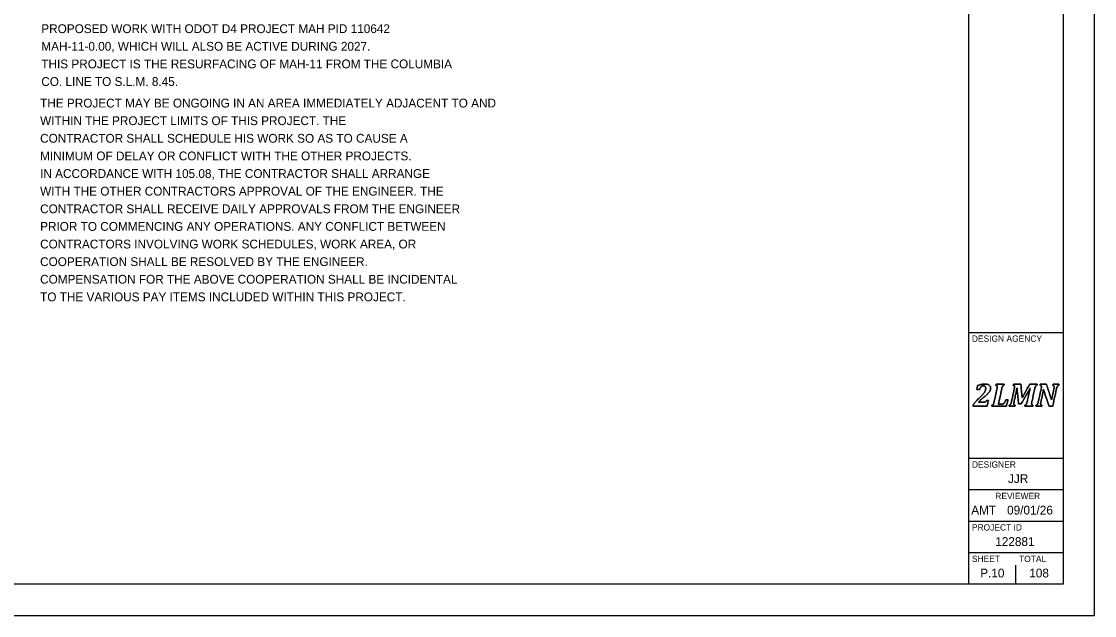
# Model space of a CAD drawing. Extents: x 0 to 34, y 0 to 22.
# Drawn here: x 16.93 to 34, y 0 to 9.44 of the extents above; entities that cross this region are included whole.
import ezdxf

# ---------------------------------------------------------------- set-up
doc = ezdxf.new("R2010")
doc.units = 0
for name, color, linetype in [('SH_Border', 7, 'Continuous'), ('SH_Cut_Line', 7, 'Continuous'), ('SH_Data', 7, 'Continuous'), ('SH_Text', 7, 'Continuous')]:
    doc.layers.add(name, color=color, linetype=linetype)

msp = doc.modelspace()

# ---------------------------------------------------------------- linework, layer by layer
at = {"layer": 'SH_Border'}
for p, q in [((32, 0.5), (32, 21.5)), ((32, 4.5), (33.5, 4.5)), ((32, 2.5), (33.5, 2.5)), ((32, 2), (33.5, 2)), ((32, 1.5), (33.5, 1.5)), ((32, 1), (33.5, 1))]:
    msp.add_line(p, q, dxfattribs=at)
msp.add_lwpolyline([(1.5, 21.5), (33.5, 21.5), (33.5, 0.5), (1.5, 0.5)], close=True, dxfattribs=at)
at = {"layer": 'SH_Cut_Line'}
msp.add_lwpolyline([(0, 0), (34, 0), (34, 22), (0, 22)], close=True, dxfattribs=at)
at = {"layer": 'SH_Data'}
for p, q in [((32.75, 3.5), (32.75, 3.5)), ((32.75, 0.5), (32.75, 0.8)), ((32.375, 0.675), (32.375, 0.675))]:
    msp.add_line(p, q, dxfattribs=at)
for points in [[(32.237, 3.388), (32.246, 3.388), (32.253, 3.389), (32.258, 3.39), (32.263, 3.392), (32.267, 3.394), (32.27, 3.397), (32.273, 3.401), (32.277, 3.408), (32.281, 3.417), (32.281, 3.417), (32.312, 3.417), (32.312, 3.417), (32.312, 3.417), (32.29, 3.326), (32.29, 3.326), (32.29, 3.326), (32.066, 3.326), (32.066, 3.326), (32.066, 3.326), (32.069, 3.343), (32.069, 3.343), (32.078, 3.358), (32.091, 3.375), (32.106, 3.394), (32.122, 3.412), (32.144, 3.435), (32.172, 3.462), (32.197, 3.486), (32.217, 3.506), (32.23, 3.521), (32.243, 3.537), (32.253, 3.551), (32.259, 3.566), (32.266, 3.58), (32.269, 3.595), (32.269, 3.61), (32.269, 3.622), (32.266, 3.632), (32.26, 3.64), (32.253, 3.647), (32.245, 3.65), (32.234, 3.65), (32.22, 3.65), (32.208, 3.646), (32.198, 3.636), (32.188, 3.627), (32.18, 3.613), (32.172, 3.593), (32.172, 3.593), (32.126, 3.593), (32.126, 3.593), (32.126, 3.593), (32.14, 3.654), (32.14, 3.654), (32.166, 3.663), (32.188, 3.669), (32.205, 3.673), (32.223, 3.676), (32.24, 3.678), (32.258, 3.678), (32.278, 3.678), (32.295, 3.675), (32.309, 3.669), (32.322, 3.664), (32.332, 3.656), (32.339, 3.646), (32.345, 3.637), (32.348, 3.626), (32.348, 3.613), (32.348, 3.602), (32.346, 3.591), (32.342, 3.581), (32.339, 3.571), (32.333, 3.56), (32.324, 3.549), (32.315, 3.539), (32.304, 3.526), (32.289, 3.513), (32.275, 3.499), (32.254, 3.482), (32.228, 3.46), (32.216, 3.45), (32.202, 3.438), (32.188, 3.425), (32.174, 3.412), (32.162, 3.4), (32.154, 3.391), (32.154, 3.391), (32.153, 3.388), (32.153, 3.388), (32.153, 3.388), (32.237, 3.388), (32.237, 3.388)], [(32.237, 3.388), (32.237, 3.388), (32.153, 3.388), (32.153, 3.388), (32.153, 3.388), (32.154, 3.391), (32.154, 3.391), (32.162, 3.4), (32.174, 3.412), (32.188, 3.425), (32.202, 3.438), (32.216, 3.45), (32.228, 3.46), (32.254, 3.482), (32.275, 3.499), (32.289, 3.513), (32.304, 3.526), (32.315, 3.539), (32.324, 3.549), (32.333, 3.56), (32.339, 3.571), (32.342, 3.581), (32.346, 3.591), (32.348, 3.602), (32.348, 3.613), (32.348, 3.626), (32.345, 3.637), (32.339, 3.646), (32.332, 3.656), (32.322, 3.664), (32.309, 3.669), (32.295, 3.675), (32.278, 3.678), (32.258, 3.678), (32.24, 3.678), (32.223, 3.676), (32.205, 3.673), (32.188, 3.669), (32.166, 3.663), (32.14, 3.654), (32.14, 3.654), (32.126, 3.593), (32.126, 3.593), (32.126, 3.593), (32.172, 3.593), (32.172, 3.593), (32.18, 3.613), (32.188, 3.627), (32.198, 3.636), (32.208, 3.646), (32.22, 3.65), (32.234, 3.65), (32.245, 3.65), (32.253, 3.647), (32.26, 3.64), (32.266, 3.632), (32.269, 3.622), (32.269, 3.61), (32.269, 3.595), (32.266, 3.58), (32.259, 3.566), (32.253, 3.551), (32.243, 3.537), (32.23, 3.521), (32.217, 3.506), (32.197, 3.486), (32.172, 3.462), (32.144, 3.435), (32.122, 3.412), (32.106, 3.394), (32.091, 3.375), (32.078, 3.358), (32.069, 3.343), (32.069, 3.343), (32.066, 3.326), (32.066, 3.326), (32.066, 3.326), (32.29, 3.326), (32.29, 3.326), (32.29, 3.326), (32.312, 3.417), (32.312, 3.417), (32.312, 3.417), (32.281, 3.417), (32.281, 3.417), (32.277, 3.408), (32.273, 3.401), (32.27, 3.397), (32.267, 3.394), (32.263, 3.392), (32.258, 3.39), (32.253, 3.389), (32.246, 3.388), (32.237, 3.388)], [(32.518, 3.356), (32.527, 3.356), (32.533, 3.357), (32.538, 3.358), (32.542, 3.36), (32.546, 3.362), (32.55, 3.365), (32.554, 3.368), (32.558, 3.372), (32.562, 3.377), (32.567, 3.382), (32.571, 3.388), (32.576, 3.397), (32.58, 3.405), (32.585, 3.415), (32.589, 3.427), (32.589, 3.427), (32.624, 3.427), (32.624, 3.427), (32.624, 3.427), (32.598, 3.326), (32.598, 3.326), (32.598, 3.326), (32.365, 3.326), (32.365, 3.326), (32.365, 3.326), (32.369, 3.343), (32.369, 3.343), (32.376, 3.345), (32.381, 3.348), (32.385, 3.351), (32.389, 3.355), (32.392, 3.36), (32.395, 3.366), (32.398, 3.373), (32.4, 3.382), (32.403, 3.395), (32.403, 3.395), (32.449, 3.605), (32.449, 3.605), (32.452, 3.615), (32.453, 3.625), (32.453, 3.635), (32.453, 3.642), (32.451, 3.647), (32.448, 3.651), (32.444, 3.654), (32.439, 3.656), (32.432, 3.657), (32.432, 3.657), (32.435, 3.674), (32.435, 3.674), (32.435, 3.674), (32.563, 3.674), (32.563, 3.674), (32.563, 3.674), (32.559, 3.657), (32.559, 3.657), (32.552, 3.655), (32.547, 3.652), (32.543, 3.649), (32.539, 3.645), (32.536, 3.64), (32.533, 3.634), (32.531, 3.627), (32.528, 3.618), (32.525, 3.605), (32.525, 3.605), (32.47, 3.356), (32.47, 3.356), (32.47, 3.356), (32.518, 3.356), (32.518, 3.356)], [(32.518, 3.356), (32.518, 3.356), (32.47, 3.356), (32.47, 3.356), (32.47, 3.356), (32.525, 3.605), (32.525, 3.605), (32.528, 3.618), (32.531, 3.627), (32.533, 3.634), (32.536, 3.64), (32.539, 3.645), (32.543, 3.649), (32.547, 3.652), (32.552, 3.655), (32.559, 3.657), (32.559, 3.657), (32.563, 3.674), (32.563, 3.674), (32.563, 3.674), (32.435, 3.674), (32.435, 3.674), (32.435, 3.674), (32.432, 3.657), (32.432, 3.657), (32.439, 3.656), (32.444, 3.654), (32.448, 3.651), (32.451, 3.647), (32.453, 3.642), (32.453, 3.635), (32.453, 3.625), (32.452, 3.615), (32.449, 3.605), (32.449, 3.605), (32.403, 3.395), (32.403, 3.395), (32.4, 3.382), (32.398, 3.373), (32.395, 3.366), (32.392, 3.36), (32.389, 3.355), (32.385, 3.351), (32.381, 3.348), (32.376, 3.345), (32.369, 3.343), (32.369, 3.343), (32.365, 3.326), (32.365, 3.326), (32.365, 3.326), (32.598, 3.326), (32.598, 3.326), (32.598, 3.326), (32.624, 3.427), (32.624, 3.427), (32.624, 3.427), (32.589, 3.427), (32.589, 3.427), (32.585, 3.415), (32.58, 3.405), (32.576, 3.397), (32.571, 3.388), (32.567, 3.382), (32.562, 3.377), (32.558, 3.372), (32.554, 3.368), (32.55, 3.365), (32.546, 3.362), (32.542, 3.36), (32.538, 3.358), (32.533, 3.357), (32.527, 3.356), (32.518, 3.356)], [(32.829, 3.674), (32.829, 3.674), (32.849, 3.461), (32.849, 3.461), (32.849, 3.461), (32.969, 3.674), (32.969, 3.674), (32.969, 3.674), (33.087, 3.674), (33.087, 3.674), (33.087, 3.674), (33.084, 3.657), (33.084, 3.657), (33.077, 3.655), (33.071, 3.652), (33.067, 3.649), (33.064, 3.645), (33.06, 3.64), (33.058, 3.634), (33.055, 3.627), (33.052, 3.618), (33.05, 3.605), (33.05, 3.605), (33.003, 3.395), (33.003, 3.395), (33.002, 3.39), (33.002, 3.387), (33.001, 3.384), (33.001, 3.382), (33.001, 3.379), (33, 3.376), (33, 3.373), (33, 3.369), (33, 3.365), (33, 3.358), (33.002, 3.353), (33.005, 3.349), (33.008, 3.346), (33.014, 3.344), (33.021, 3.343), (33.021, 3.343), (33.018, 3.326), (33.018, 3.326), (33.018, 3.326), (32.89, 3.326), (32.89, 3.326), (32.89, 3.326), (32.893, 3.343), (32.893, 3.343), (32.9, 3.345), (32.906, 3.348), (32.91, 3.351), (32.914, 3.355), (32.917, 3.36), (32.919, 3.366), (32.922, 3.373), (32.925, 3.382), (32.928, 3.395), (32.928, 3.395), (32.951, 3.502), (32.951, 3.502), (32.954, 3.513), (32.957, 3.529), (32.962, 3.548), (32.967, 3.568), (32.972, 3.588), (32.978, 3.609), (32.978, 3.609), (32.973, 3.609), (32.973, 3.609), (32.965, 3.594), (32.957, 3.579), (32.948, 3.563), (32.948, 3.563), (32.833, 3.364), (32.833, 3.364), (32.833, 3.364), (32.792, 3.364), (32.792, 3.364), (32.792, 3.364), (32.775, 3.518), (32.775, 3.518), (32.773, 3.537), (32.772, 3.554), (32.77, 3.569), (32.769, 3.583), (32.768, 3.597), (32.768, 3.611), (32.768, 3.611), (32.764, 3.611), (32.764, 3.611), (32.761, 3.596), (32.758, 3.578), (32.755, 3.558), (32.751, 3.538), (32.747, 3.521), (32.744, 3.507), (32.744, 3.507), (32.72, 3.395), (32.72, 3.395), (32.719, 3.39), (32.718, 3.387), (32.718, 3.384), (32.717, 3.382), (32.717, 3.379), (32.717, 3.376), (32.717, 3.373), (32.716, 3.369), (32.716, 3.365), (32.716, 3.358), (32.718, 3.353), (32.721, 3.349), (32.725, 3.346), (32.73, 3.344), (32.738, 3.343), (32.738, 3.343), (32.734, 3.326), (32.734, 3.326), (32.734, 3.326), (32.641, 3.326), (32.641, 3.326), (32.641, 3.326), (32.644, 3.343), (32.644, 3.343), (32.651, 3.345), (32.657, 3.348), (32.661, 3.351), (32.665, 3.355), (32.668, 3.36), (32.67, 3.366), (32.673, 3.373), (32.676, 3.382), (32.679, 3.395), (32.679, 3.395), (32.725, 3.605), (32.725, 3.605), (32.727, 3.615), (32.728, 3.625), (32.728, 3.635), (32.728, 3.642), (32.727, 3.647), (32.723, 3.651), (32.72, 3.654), (32.715, 3.656), (32.707, 3.657), (32.707, 3.657), (32.711, 3.674), (32.711, 3.674), (32.711, 3.674), (32.829, 3.674), (32.829, 3.674)], [(32.829, 3.674), (32.829, 3.674), (32.711, 3.674), (32.711, 3.674), (32.711, 3.674), (32.707, 3.657), (32.707, 3.657), (32.715, 3.656), (32.72, 3.654), (32.723, 3.651), (32.727, 3.647), (32.728, 3.642), (32.728, 3.635), (32.728, 3.625), (32.727, 3.615), (32.725, 3.605), (32.725, 3.605), (32.679, 3.395), (32.679, 3.395), (32.676, 3.382), (32.673, 3.373), (32.67, 3.366), (32.668, 3.36), (32.665, 3.355), (32.661, 3.351), (32.657, 3.348), (32.651, 3.345), (32.644, 3.343), (32.644, 3.343), (32.641, 3.326), (32.641, 3.326), (32.641, 3.326), (32.734, 3.326), (32.734, 3.326), (32.734, 3.326), (32.738, 3.343), (32.738, 3.343), (32.73, 3.344), (32.725, 3.346), (32.721, 3.349), (32.718, 3.353), (32.716, 3.358), (32.716, 3.365), (32.716, 3.369), (32.717, 3.373), (32.717, 3.376), (32.717, 3.379), (32.717, 3.382), (32.718, 3.384), (32.718, 3.387), (32.719, 3.39), (32.72, 3.395), (32.72, 3.395), (32.744, 3.507), (32.744, 3.507), (32.747, 3.521), (32.751, 3.538), (32.755, 3.558), (32.758, 3.578), (32.761, 3.596), (32.764, 3.611), (32.764, 3.611), (32.768, 3.611), (32.768, 3.611), (32.768, 3.597), (32.769, 3.583), (32.77, 3.569), (32.772, 3.554), (32.773, 3.537), (32.775, 3.518), (32.775, 3.518), (32.792, 3.364), (32.792, 3.364), (32.792, 3.364), (32.833, 3.364), (32.833, 3.364), (32.833, 3.364), (32.948, 3.563), (32.948, 3.563), (32.957, 3.579), (32.965, 3.594), (32.973, 3.609), (32.973, 3.609), (32.978, 3.609), (32.978, 3.609), (32.972, 3.588), (32.967, 3.568), (32.962, 3.548), (32.957, 3.529), (32.954, 3.513), (32.951, 3.502), (32.951, 3.502), (32.928, 3.395), (32.928, 3.395), (32.925, 3.382), (32.922, 3.373), (32.919, 3.366), (32.917, 3.36), (32.914, 3.355), (32.91, 3.351), (32.906, 3.348), (32.9, 3.345), (32.893, 3.343), (32.893, 3.343), (32.89, 3.326), (32.89, 3.326), (32.89, 3.326), (33.018, 3.326), (33.018, 3.326), (33.018, 3.326), (33.021, 3.343), (33.021, 3.343), (33.014, 3.344), (33.008, 3.346), (33.005, 3.349), (33.002, 3.353), (33, 3.358), (33, 3.365), (33, 3.369), (33, 3.373), (33, 3.376), (33.001, 3.379), (33.001, 3.382), (33.001, 3.384), (33.002, 3.387), (33.002, 3.39), (33.003, 3.395), (33.003, 3.395), (33.05, 3.605), (33.05, 3.605), (33.052, 3.618), (33.055, 3.627), (33.058, 3.634), (33.06, 3.64), (33.064, 3.645), (33.067, 3.649), (33.071, 3.652), (33.077, 3.655), (33.084, 3.657), (33.084, 3.657), (33.087, 3.674), (33.087, 3.674), (33.087, 3.674), (32.969, 3.674), (32.969, 3.674), (32.969, 3.674), (32.849, 3.461), (32.849, 3.461), (32.849, 3.461), (32.829, 3.674), (32.829, 3.674)], [(33.137, 3.674), (33.137, 3.674), (33.234, 3.674), (33.234, 3.674), (33.234, 3.674), (33.283, 3.53), (33.283, 3.53), (33.296, 3.49), (33.307, 3.456), (33.315, 3.426), (33.315, 3.426), (33.318, 3.426), (33.318, 3.426), (33.323, 3.455), (33.329, 3.488), (33.337, 3.523), (33.337, 3.523), (33.355, 3.605), (33.355, 3.605), (33.357, 3.615), (33.358, 3.625), (33.358, 3.635), (33.358, 3.642), (33.357, 3.647), (33.353, 3.651), (33.35, 3.654), (33.345, 3.656), (33.337, 3.657), (33.337, 3.657), (33.341, 3.674), (33.341, 3.674), (33.341, 3.674), (33.434, 3.674), (33.434, 3.674), (33.434, 3.674), (33.431, 3.657), (33.431, 3.657), (33.424, 3.655), (33.418, 3.652), (33.414, 3.649), (33.41, 3.645), (33.407, 3.64), (33.405, 3.634), (33.402, 3.627), (33.399, 3.618), (33.396, 3.605), (33.396, 3.605), (33.335, 3.326), (33.335, 3.326), (33.335, 3.326), (33.277, 3.326), (33.277, 3.326), (33.277, 3.326), (33.216, 3.504), (33.216, 3.504), (33.211, 3.518), (33.207, 3.531), (33.204, 3.543), (33.2, 3.556), (33.195, 3.571), (33.19, 3.59), (33.19, 3.59), (33.186, 3.59), (33.186, 3.59), (33.185, 3.579), (33.182, 3.563), (33.179, 3.543), (33.175, 3.523), (33.17, 3.501), (33.165, 3.478), (33.165, 3.478), (33.147, 3.395), (33.147, 3.395), (33.146, 3.39), (33.145, 3.387), (33.145, 3.384), (33.144, 3.382), (33.144, 3.379), (33.144, 3.376), (33.143, 3.373), (33.143, 3.369), (33.143, 3.365), (33.143, 3.358), (33.145, 3.353), (33.148, 3.349), (33.152, 3.346), (33.157, 3.344), (33.164, 3.343), (33.164, 3.343), (33.161, 3.326), (33.161, 3.326), (33.161, 3.326), (33.067, 3.326), (33.067, 3.326), (33.067, 3.326), (33.071, 3.343), (33.071, 3.343), (33.078, 3.345), (33.083, 3.348), (33.087, 3.351), (33.091, 3.355), (33.094, 3.36), (33.097, 3.366), (33.1, 3.373), (33.102, 3.382), (33.105, 3.395), (33.105, 3.395), (33.151, 3.605), (33.151, 3.605), (33.154, 3.615), (33.155, 3.625), (33.155, 3.635), (33.155, 3.642), (33.153, 3.647), (33.15, 3.651), (33.146, 3.654), (33.141, 3.656), (33.134, 3.657), (33.134, 3.657), (33.137, 3.674), (33.137, 3.674)], [(33.137, 3.674), (33.137, 3.674), (33.134, 3.657), (33.134, 3.657), (33.141, 3.656), (33.146, 3.654), (33.15, 3.651), (33.153, 3.647), (33.155, 3.642), (33.155, 3.635), (33.155, 3.625), (33.154, 3.615), (33.151, 3.605), (33.151, 3.605), (33.105, 3.395), (33.105, 3.395), (33.102, 3.382), (33.1, 3.373), (33.097, 3.366), (33.094, 3.36), (33.091, 3.355), (33.087, 3.351), (33.083, 3.348), (33.078, 3.345), (33.071, 3.343), (33.071, 3.343), (33.067, 3.326), (33.067, 3.326), (33.067, 3.326), (33.161, 3.326), (33.161, 3.326), (33.161, 3.326), (33.164, 3.343), (33.164, 3.343), (33.157, 3.344), (33.152, 3.346), (33.148, 3.349), (33.145, 3.353), (33.143, 3.358), (33.143, 3.365), (33.143, 3.369), (33.143, 3.373), (33.144, 3.376), (33.144, 3.379), (33.144, 3.382), (33.145, 3.384), (33.145, 3.387), (33.146, 3.39), (33.147, 3.395), (33.147, 3.395), (33.165, 3.478), (33.165, 3.478), (33.17, 3.501), (33.175, 3.523), (33.179, 3.543), (33.182, 3.563), (33.185, 3.579), (33.186, 3.59), (33.186, 3.59), (33.19, 3.59), (33.19, 3.59), (33.195, 3.571), (33.2, 3.556), (33.204, 3.543), (33.207, 3.531), (33.211, 3.518), (33.216, 3.504), (33.216, 3.504), (33.277, 3.326), (33.277, 3.326), (33.277, 3.326), (33.335, 3.326), (33.335, 3.326), (33.335, 3.326), (33.396, 3.605), (33.396, 3.605), (33.399, 3.618), (33.402, 3.627), (33.405, 3.634), (33.407, 3.64), (33.41, 3.645), (33.414, 3.649), (33.418, 3.652), (33.424, 3.655), (33.431, 3.657), (33.431, 3.657), (33.434, 3.674), (33.434, 3.674), (33.434, 3.674), (33.341, 3.674), (33.341, 3.674), (33.341, 3.674), (33.337, 3.657), (33.337, 3.657), (33.345, 3.656), (33.35, 3.654), (33.353, 3.651), (33.357, 3.647), (33.358, 3.642), (33.358, 3.635), (33.358, 3.625), (33.357, 3.615), (33.355, 3.605), (33.355, 3.605), (33.337, 3.523), (33.337, 3.523), (33.329, 3.488), (33.323, 3.455), (33.318, 3.426), (33.318, 3.426), (33.315, 3.426), (33.315, 3.426), (33.307, 3.456), (33.296, 3.49), (33.283, 3.53), (33.283, 3.53), (33.234, 3.674), (33.234, 3.674), (33.234, 3.674), (33.137, 3.674), (33.137, 3.674)]]:
    msp.add_open_spline(points, degree=3, dxfattribs=at)

# ---------------------------------------------------------------- texts
for s, height, p in [('DESIGN AGENCY', 0.1, (32.05, 4.35)), ('DESIGNER', 0.1, (32.05, 2.35)), ('JJR', 0.14, (32.624, 2.105)), ('REVIEWER', 0.1, (32.422, 1.85)), ('AMT', 0.14, (32.039, 1.605)), ('09/01/26', 0.14, (32.609, 1.605)), ('PROJECT ID', 0.1, (32.05, 1.35)), ('122881', 0.14, (32.421, 1.105)), ('SHEET', 0.1, (32.05, 0.85)), ('TOTAL', 0.1, (32.8, 0.85)), ('P.10', 0.14, (32.182, 0.605)), ('108', 0.14, (32.962, 0.605))]:
    msp.add_text(s, height=height, dxfattribs=at).set_placement(p)
at = {"layer": 'SH_Text'}
for s, p in [('PROPOSED WORK WITH ODOT D4 PROJECT MAH PID 110642', (17.25, 9.255)), ('MAH-11-0.00, WHICH WILL ALSO BE ACTIVE DURING 2027.', (17.25, 8.975)), ('THIS PROJECT IS THE RESURFACING OF MAH-11 FROM THE COLUMBIA', (17.25, 8.695)), ('CO. LINE TO S.L.M. 8.45.', (17.25, 8.415)), ('THE PROJECT MAY BE ONGOING IN AN AREA IMMEDIATELY ADJACENT TO AND', (17.231, 8.073)), ('WITHIN THE PROJECT LIMITS OF THIS PROJECT. THE', (17.231, 7.793)), ('CONTRACTOR SHALL SCHEDULE HIS WORK SO AS TO CAUSE A', (17.231, 7.513)), ('MINIMUM OF DELAY OR CONFLICT WITH THE OTHER PROJECTS.', (17.231, 7.233)), ('IN ACCORDANCE WITH 105.08, THE CONTRACTOR SHALL ARRANGE', (17.231, 6.953)), ('WITH THE OTHER CONTRACTORS APPROVAL OF THE ENGINEER. THE', (17.231, 6.673)), ('CONTRACTOR SHALL RECEIVE DAILY APPROVALS FROM THE ENGINEER', (17.231, 6.393)), ('PRIOR TO COMMENCING ANY OPERATIONS. ANY CONFLICT BETWEEN', (17.231, 6.113)), ('CONTRACTORS INVOLVING WORK SCHEDULES, WORK AREA, OR', (17.231, 5.833)), ('COOPERATION SHALL BE RESOLVED BY THE ENGINEER.', (17.231, 5.553)), ('COMPENSATION FOR THE ABOVE COOPERATION SHALL BE INCIDENTAL', (17.231, 5.273)), ('TO THE VARIOUS PAY ITEMS INCLUDED WITHIN THIS PROJECT.', (17.231, 4.993))]:
    msp.add_text(s, height=0.14, dxfattribs=at).set_placement(p)

doc.saveas('drawing.dxf')
